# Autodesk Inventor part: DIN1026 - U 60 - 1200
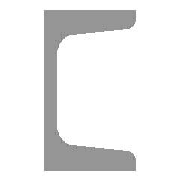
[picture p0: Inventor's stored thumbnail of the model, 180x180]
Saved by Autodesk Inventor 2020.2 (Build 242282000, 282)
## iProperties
Manager: www.cadconsulting.pl
Company: Fabian Stasiak CAD Consulting
Created: 2014-02
Part Number: DIN1026 - U 60 - 1200
Material: Stal, miękka
Description: Ceownik
Document SubType Name: Modeling
Standard: DIN 1026
Designer: F.Stasiak
Standard Revision: 2000
Standards Organization: DIN
Language: pl-PL
Size Designation: U 60 - 1200
Categories: <MemberInstance><Categories><Category DisplayName="Kształtowniki konstrukcyjne" InternalName="089c4875-fa83-4c05-b084-43b9cc11f5ed" Mnemonic="GRDR"><CategoryPar
Stock Number: U 60
Density: 7.85 g/cm^3
Appearance: Częściowo polerowana
Catalog Web Link: www.expertbooks.pl
IsCustomPart: 1
G_L: 1200,000 mm
Author: F.Stasiak
Subject: Zbiór ćwiczeń. Autodesk Inventor 2020. Kurs Professional
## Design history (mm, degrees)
node "Płaszczyzna początkowa"
node "Płaszczyzna końcowa"
sketch "Szkic"
  geometry: L1 (0, 0)-(0, 30); L2 (0, 30)-(30, 30); L3 (30, 30)-(30, 27.97); L4 (27.239, 24.979)-(11.522, 23.722); L5 (6, 17.741)-(6, 0); L6 (6, 0)-(0, 0); L7 (15, 30)-(15, 24); L8 (30, 25.2)-(30, 24); L9 (30, 24)-(15, 24); L10 (0, 15)-(0, -27); L11 (-5.539, 0)-(16.007, 0); L12 (0, 0)-(0, -30); L13 (0, -30)-(30, -30); L14 (30, -30)-(30, -27.97); L15 (27.239, -24.979)-(11.522, -23.722); L16 (6, -17.741)-(6, 0); L17 (0, 23.4)-(0, -35.4) reference; L18 (-9.848, 0)-(20.316, 0) reference; A1 r 6 centre (12, 17.741) between (11.522, 23.722) and (6, 17.741); A2 r 6 centre (12, -17.741) between (6, -17.741) and (11.522, -23.722); A3 r 3 centre (27, 27.97) between (27.239, 24.979) and (30, 27.97); A4 r 3 centre (27, -27.97) between (30, -27.97) and (27.239, -24.979); 5 further points
  constraints: 32 end point, 10 point on line, 8 point on circle, 8 tangent, 6 symmetric about line, 4 centre point, 4 parallel, 3 collinear, 3 perpendicular, 2 equal radius, 2 midpoint, 5 other
  dimensions: "d0" = 6 distance between parallel lines of L1 L5 (= G_T); "d1" = 30 distance between parallel lines of L6 L2 (= 0.5 x G_H); "d2" = 30 distance between parallel lines of L3 L1 (= G_W); "d3" = 6 distance of L2.end L8.end (= G_T1); "d4" = 15 distance of L7.start L2.end (= G_C); "d5" = 1.2 distance of L8.start L8.end (computed from G_NG, G_C); "d23" = 6 radius of A1 (= G_IR); "d24" = 3 radius of A3 (= G_ER); "d25" = 0 distance between parallel lines of L10 L12 (computed from ex)
extrude "Bryła" new body sketch "Szkic" stored distance "d6" = 1200 (= G_L); taper "d7" = 0 deg
node "Driven Length"
  sketch "Sketch3"
    geometry: L1 (0, 0)-(10, 0) reference
    constraints: 2 end point, 1 horizontal
  workplane "Work Plane3"
  sketch "Sketch4"
    geometry: L1 (-2, 0)-(12, 0) reference; L2 (-2, 1200)-(12, 1200) reference
    dimensions: "d29" = 1200 distance between parallel lines of L1 L2 (derived)
body "Solid1"
other parameters: "G_W" = 30 [user parameter; used in 1 equation term], "G_T" = 6 [user parameter; used in 1 equation term], "G_T1" = 6 [user parameter; used in 1 equation term], "G_NG" = 0.8 [user parameter; used in 1 equation term], "G_ER" = 3 [user parameter; used in 1 equation term], "G_IR" = 6 [user parameter; used in 1 equation term], "G_C" = 15 [user parameter; used in 2 equation terms], "G_L" = 1200 (= d29) [user parameter; used in 1 equation term], "ex" = 0 [user parameter; used in 1 equation term], "G_OFFSET_START" = 0 [user parameter; used in 1 equation term], "G_OFFSET_END" = 0 [user parameter; used in 1 equation term], "d26" = 0 (computed from G_OFFSET_START), "d28" = 90 deg
